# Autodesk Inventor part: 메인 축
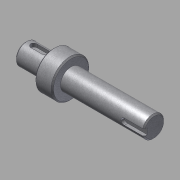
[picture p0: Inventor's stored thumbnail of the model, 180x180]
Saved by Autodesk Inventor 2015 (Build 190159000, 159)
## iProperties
Created: 2014-10
Part Number: 메인 축
Document SubType Name: Modeling
Designer: KYOUNG IL JANG
Density: 7.86 g/cm^3
Mass: 230.24 g
Surface Area: 74.3518 cm^2
Volume: 29.2926 cm^3
Material: 강철, 연강
Appearance: 금속-강(스테인리스, 브러시됨)
Author: SeoGD™ [www.esajin.kr]
Revision Number: 1
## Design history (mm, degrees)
sketch "스케치1"
  geometry: L1 (10.497, -57.5)-(112.497, -57.5); L2 (10.497, -66)-(32.497, -66); L3 (32.497, -72.5)-(46.5, -72.5); L4 (46.5, -66)-(112.497, -66); L5 (112.497, -66)-(112.497, -57.5); L6 (10.497, -66)-(10.497, -57.5); L7 (46.5, -69.749)-(46.5, -45.251) reference; L8 (46.5, -72.5)-(46.5, -66); L9 (32.497, -72.5)-(32.497, -66); L10 (32.497, -35)-(32.497, -80) reference; 3 further points
  constraints: 16 end point, 3 point on line, 2 parallel, 2 perpendicular, 1 collinear, 1 horizontal, 1 midpoint
  dimensions: "d0" = 17 diameter of L4 L1; "d1" = 30 diameter of L3 L1; "d2" = 22 distance of L2.start L2.end; "d3" = 65.99692 distance of L4.start L4.end (derived); "d5" = 17 diameter of L2 L1; "d19" = 80 distance between parallel lines of L5 L9
revolve "회전1" sketch "스케치1" stored, may be unused: angle "d4" = 90 deg
chamfer "모따기1" distance "d6" = 1; stored, may be unused: second distance "d7" = 2, angle "d8" = 45 deg
node "작업 평면1"
sketch "스케치2"
  geometry: L1 (-11, -7.5)-(-11, 7.5) reference; L2 (-4.5, 2.5)-(4.5, 2.5); L3 (4.5, -2.5)-(-4.5, -2.5); A1 r 2.5 centre (4.5, 0) between (4.5, -2.5) and (4.5, 2.5); A2 r 2.5 centre (-4.5, 0) between (-4.5, 2.5) and (-4.5, -2.5); 2 further points
  constraints: 4 end point, 4 point on circle, 4 tangent, 2 centre point, 1 horizontal alignment, 1 midpoint, 1 parallel, 1 perpendicular
  dimensions: "d9" = 5 distance between parallel lines of L3 L2; "d10" = 14 dimension on A1 A2; "d11" = 4 distance edge to line of A2 L1
extrude "돌출1" cut sketch "스케치2" distance "d12" = 3; taper "d13" = 0 deg
node "작업 평면2"
sketch "스케치3"
  geometry: L1 (32.998, 7.5)-(32.998, -7.5) reference; L2 (32.998, 2.5)-(17.498, 2.5); L3 (17.498, -2.5)-(32.998, -2.5); A1 r 2.5 centre (17.498, 0) between (17.498, 2.5) and (17.498, -2.5); 2 further points
  constraints: 4 end point, 2 perpendicular, 2 point on circle, 2 point on line, 2 tangent, 1 centre point, 1 horizontal alignment, 1 midpoint
  dimensions: "d14" = 5 distance between parallel lines of L3 L2; "d15" = 18 dimension on A1 L1
extrude "돌출2" cut sketch "스케치3" distance "d16" = 3; taper "d17" = 0 deg
node "솔리드1"
node "참조4"
node "참조5"
